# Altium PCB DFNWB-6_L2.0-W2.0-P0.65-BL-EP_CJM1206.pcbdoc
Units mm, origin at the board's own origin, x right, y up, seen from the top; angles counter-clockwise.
Board outline 15 x 15.35 mm, 2 copper layers (Top Layer, Bottom Layer), stack 0 mm thick; 1 components, 0 nets, 8 pads, 0 vias.
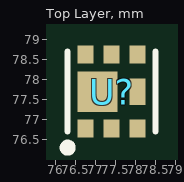
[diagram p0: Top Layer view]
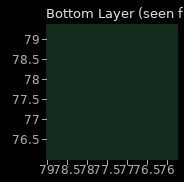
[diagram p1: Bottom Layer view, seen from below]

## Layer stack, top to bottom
Top Layer: signal copper (thickness not stored)
Bottom Layer: signal copper (thickness not stored)

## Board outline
84.85,69.85 69.85,69.85 69.85,85.2 84.85,85.2

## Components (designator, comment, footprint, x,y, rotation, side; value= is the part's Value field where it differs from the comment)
U? "" DFNWB-6_L2.0-W2.0-P0.65-BL-EP_CJM1206 77.4,77.7 r0 top

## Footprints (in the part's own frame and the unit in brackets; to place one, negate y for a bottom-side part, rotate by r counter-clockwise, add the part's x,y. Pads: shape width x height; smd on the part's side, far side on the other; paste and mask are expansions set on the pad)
DFNWB-6_L2.0-W2.0-P0.65-BL-EP_CJM1206 [mm]
  rect 0.4x0.45 smd: 1(-0.65,-0.925) 2(0,-0.925) 3(0.65,-0.925) 4(0.65,0.925) 5(0,0.925) 6(-0.65,0.925)
  rect 1x1.02 smd: 7(-0.35,0)
  rect 0.4x0.66 smd: 8(0.65,0)
  silkscreen extent -1.2,-1.5 1.1,1

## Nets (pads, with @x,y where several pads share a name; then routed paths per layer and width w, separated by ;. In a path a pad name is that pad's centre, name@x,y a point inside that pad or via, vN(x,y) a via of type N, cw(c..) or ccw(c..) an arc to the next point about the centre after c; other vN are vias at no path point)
pads on no net: U?.1 U?.2 U?.3 U?.4 U?.5 U?.6 U?.7 U?.8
